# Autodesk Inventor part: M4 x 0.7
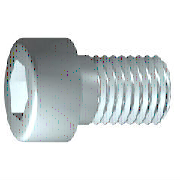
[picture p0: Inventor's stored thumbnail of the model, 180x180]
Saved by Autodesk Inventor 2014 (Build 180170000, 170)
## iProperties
IsCustomPart: 0
Created: 2015-10
Part Number: M4 x 0.7
Material: 강, 연강
Description: 6각머리 태핑 나사
Document SubType Name: Modeling
Standard: KS B 1003
Designer: mdu
Standards Organization: KS
Language: ko-KR
Size Designation: M 4 x 25
Categories: <MemberInstance><Categories><Category DisplayName="조임쇠" InternalName="e4da775c-781d-43d5-af7c-5136215cf5a6" Mnemonic="FSTN"><Category DisplayName="볼트" InternalN
Density: 1 g/cm^3
Appearance: 강철
Author: mdu
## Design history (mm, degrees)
sketch "스케치1"
  geometry: L1 (-1, 0)-(25, 0); L2 (25, 0)-(25, 2); L3 (25, 2)-(1.75, 2); L4 (1.75, 2)-(1.32, 2); L5 (1.32, 2)-(0, 2); L6 (0, 2)-(0, 3.5); L7 (0, 3.5)-(-4, 3.5); L8 (-4, 3.5)-(-4, 1.732); L9 (-4, 1.732)-(-2, 1.732); L10 (-2, 1.732)-(-1, 0); L11 (-9.8, 0)-(30.8, 0) reference; L12 (0, -0.7)-(0, 4.2) reference; L13 (1.75, 2)-(0, 2)
  constraints: 22 end point, 6 parallel, 2 collinear, 2 perpendicular, 1 horizontal, 1 point on line
  dimensions: "d1" = 23.25 distance from line of L3.end L2 (= GEL); "d2" = 0.42952 distance of L4.end L3.end (computed from GAL); "d3" = 4 distance between parallel lines of L8 L6 (= KOH); "d4" = 2 distance of L8.end L9.end (= INTI); "d5" = 60 deg angle of L10 L1; "d6" = 4 diameter of L3 L1 (= GD); "d7" = 4 diameter of L5 L1 (= BDM); "d8" = 3.4641 diameter of L9 L1 (= 1.1547 x SW); "d9" = 7 diameter of L7 L1 (= KOD); "d26" = 25 distance between parallel lines of L12 L2 (= NLG)
revolve "본체" sketch "스케치1" stored, may be unused: angle "d10" = 90 deg
sketch "스케치2"
  geometry: L1 (0, -4.9)-(0, 4.9) reference; L2 (-4.9, 0)-(4.9, 0) reference; L3 (1.732, 0)-(0.866, -1.5); L4 (0.866, -1.5)-(-0.866, -1.5); L5 (-0.866, -1.5)-(-1.732, 0); L6 (-1.732, 0)-(-0.866, 1.5); L7 (-0.866, 1.5)-(0.866, 1.5); L8 (0.866, 1.5)-(1.732, 0); 2 further points
  constraints: 12 end point, 1 coincident, 1 horizontal alignment, 1 point on line, 12 other
extrude "슬롯" join sketch "스케치2" stored distance "d11" = 10; taper "d12" = 0 deg
workplane "Work Plane1"
fillet "Fillet2" dims "d30" = 0.1 (= R)
body "Solid1"
fillet "모깎기1" dims "d17" = 0.4 (= RR)
feature "스레드" dims "d13" = 23.25 (= GEL), "d14" = 0
chamfer "모따기1" distance "d15" = 0.42941 (= -0.5 x SPD + 0.5 x GD); stored, may be unused: second distance "d16" = 0.42941 (= GUL), angle "d27" = 45 deg
other parameters: "GD" = 4 (= NND) [user parameter; used in 2 equation terms], "NLG" = 25 [user parameter; used in 1 equation term], "GEL" = 23.25 [user parameter; used in 2 equation terms], "KOD" = 7 [user parameter; used in 1 equation term], "KOH" = 4 [user parameter; used in 1 equation term], "INTI" = 2 [user parameter; used in 1 equation term], "GAL" = 0.42941 (= 0.61345 x PTC) [user parameter; used in 1 equation term], "GUL" = 0.42941 (= 0.61345 x PTC) [user parameter; used in 1 equation term], "BDM" = 4 (= NND) [user parameter; used in 1 equation term], "SW" = 3 [user parameter; used in 2 equation terms], "RR" = 0.4 [user parameter; used in 1 equation term], "SPD" = 3.14117 (= NND - 1.2269 x PTC) [user parameter; used in 1 equation term], "d19" = 0, "d28" = 0, "d29" = 0, "R" = 0.1 [user parameter; used in 1 equation term], "PHH" = 0.2 [user parameter], "GD1" = 3.14117 (= THREADDIA - 1.2269 x PTC) [user parameter], "THREADDIA" = 4 [user parameter; used in 1 equation term], "FAWI" = 45 deg [user parameter], "TPU" = 14.28571 (computed from PTC) [user parameter], "PTC" = 0.7 [user parameter; used in 5 equation terms], "NND" = 4 [user parameter; used in 3 equation terms], "TOA" = 30 deg [user parameter], "E0" = 3.465 (= 1.155 x SW) [user parameter]
